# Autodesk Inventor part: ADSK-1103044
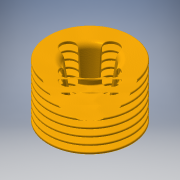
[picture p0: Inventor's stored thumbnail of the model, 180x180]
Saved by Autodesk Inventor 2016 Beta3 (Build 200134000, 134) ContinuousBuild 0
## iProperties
Shininess: 41.0
Length Units: 11272
Angle Units: 11279
Time Units: 11290
Mass Units: 11286
Length Display Precision: 4
Angle Display Precision: 2
Compacted: True
Created: 2000-07
Part Number: ADSK-1103044
Document SubType Name: Modeling
Description: ENGINE HEAD
Mass: 37.1194 g
Surface Area: 215.954 cm^2
Volume: 13.6972 cm^3
Density: 2.71 g/cm^3
Material: Aluminum-6061
Appearance: Yellow
Density: 0.0
Volumn: 0.0
Area: 0.0
PropertySet Name: Model Information
Control State: 0
Master: False
Checked Out: False
Author: Autodesk, Inc.
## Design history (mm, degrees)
node "Revolution1" dims "d6" = 90 deg
  sketch "Sketch2"
    geometry: L1 (17.699, 35.694)-(17.699, 61.094); L2 (17.699, 61.094)-(-5.161, 61.094); L3 (-5.161, 31.884)-(2.459, 31.884); L4 (2.459, 31.884)-(2.459, 35.694); L5 (2.459, 35.694)-(17.699, 35.694); L6 (-5.161, 61.094)-(-5.161, 31.884)
    constraints: 12 end point, 4 perpendicular, 1 parallel, 1 vertical, 1 other
    dimensions: "d0" = 45.72 diameter of L2.end L1; "d1" = 30.48 diameter of L4 L1; "d3" = 29.21 distance between parallel lines of L2 L3; "d5" = 3.81 distance of L3.end L4.end
workaxis "Work Axis1"
workplane "Work Plane1"
workplane "Work Plane3"
node "Revolution2" dims "d12" = 90 deg
  sketch "Sketch3"
    geometry: L1 (0, -20.447)-(0, 20.447) reference; L2 (15.24, -10.795)-(-15.24, -10.795) reference; L3 (-5.999, -10.795)-(-5.999, -8.255); L4 (-5.999, -8.255)-(-7.938, -8.255); L5 (-7.938, -8.255)-(-11.15, 14.605); L6 (22.86, 14.605)-(-22.86, 14.605) reference; L7 (-5.999, -10.795)-(0, -10.795); L8 (-11.15, 14.605)-(0, 14.605); L9 (0, 14.605)-(0, -10.795)
    constraints: 12 end point, 3 perpendicular, 2 midpoint, 2 point on line
    dimensions: "d8" = 11.99896 diameter of L3 L1; "d9" = 2.54 distance between parallel lines of L2 L4; "d10" = 8 deg angle of L1 L5; "d11" = 15.875 diameter of L4.end L1
node "Fillet1" dims "d13" = 3.175
node "Extrusion1" dims "d16" = 25.4, "d17" = 0
  sketch "Sketch4" dims "d14" = 11.5
    geometry: C1 r 22.86 at (0, 0) reference; C2 r 13.91 at (0, 0) reference; C3 r 4.128 at (0, 11.5); 1 further point
    constraints: 2 vertical alignment, 1 centre point, 1 coincident, 2 other
    dimensions: "d15" = 8.255 diameter of C3
node "Circular Pattern1" dims "d18" = 40, "d20" = 90 deg
workplane "Work Plane2"
node "Revolution3" dims "d46" = 90 deg
  sketch "Sketch5"
    geometry: L1 (11.872, 10.766)-(-8.255, 7.938) reference; L2 (14.605, -22.86)-(14.605, 22.86) reference; L3 (-13.272, 25.4)-(-10.605, 25.4); L4 (-10.605, 25.4)-(-10.605, 16.906); L5 (-13.272, 16.906)-(-13.272, 25.4); L6 (-9.335, 25.4)-(-6.668, 25.4); L7 (-6.668, 25.4)-(-6.668, 10.16); L8 (-6.668, 10.16)-(-9.335, 10.16); L9 (-9.335, 10.16)-(-9.335, 25.4); L10 (-5.398, 25.4)-(-2.731, 25.4); L11 (-2.731, 25.4)-(-2.731, 10.477); L12 (-2.731, 10.477)-(-5.398, 10.477); L13 (-5.398, 10.477)-(-5.398, 25.4); L14 (-1.461, 25.4)-(1.206, 25.4); L15 (1.206, 25.4)-(1.206, 10.795); L16 (1.206, 10.795)-(-1.461, 10.795); L17 (-1.461, 10.795)-(-1.461, 25.4); L18 (2.476, 25.4)-(5.143, 25.4); L19 (5.143, 25.4)-(5.143, 11.112); L20 (5.143, 11.112)-(2.476, 11.112); L21 (2.476, 11.112)-(2.476, 25.4); L22 (6.413, 25.4)-(9.08, 25.4); L23 (9.08, 25.4)-(9.08, 11.43); L24 (9.08, 11.43)-(6.413, 11.43); L25 (6.413, 11.43)-(6.413, 25.4); L26 (10.35, 25.4)-(13.017, 25.4); L27 (13.017, 25.4)-(13.017, 11.747); L28 (13.017, 11.747)-(10.35, 11.747); L29 (10.35, 11.747)-(10.35, 25.4); L30 (-20.447, 0)-(20.447, 0) reference; L31 (-10.605, 16.906)-(-13.272, 16.906)
    constraints: 56 end point, 13 parallel, 8 perpendicular, 7 horizontal, 6 collinear, 6 point on line
    dimensions: "d22" = 2.667 distance between parallel lines of L27 L29; "d23" = 1.5875 distance between parallel lines of L2 L27; "d24" = 1.27 distance between parallel lines of L29 L23; "d25" = 1.27 distance between parallel lines of L25 L19 (= d24); "d26" = 1.27 distance between parallel lines of L21 L15 (= d24); "d27" = 1.27 distance between parallel lines of L17 L11 (= d29); "d28" = 1.27 distance between parallel lines of L7 L13; "d29" = 1.27 distance between parallel lines of L9 L4 (= d24); "d33" = 25.4 distance from line of L30 L26.end; "d38" = 0.3175 vertical distance of L7.end L12.end (= d37); "d39" = 0.3175 vertical distance of L11.end L16.end (= d38); "d40" = 0.3175 vertical distance of L15.end L19.end (= d39); "d41" = 0.3175 vertical distance of L19.end L23.end (= d40); "d42" = 0.3175 vertical distance of L23.end L27.end (= d41)
node "Extrusion2" dims "d48" = 1.5875, "d49" = 0
  sketch "Sketch6"
    geometry: A1 r 4.128 centre (0, 11.5) between (-3.609, 9.497) and (-1.721, 7.749) reference; 2 further points
    constraints: 1 coincident, 3 other
node "Circular Pattern3" dims "d61" = 40, "d63" = 360 deg
node "Fillet3" dims "d67" = 0.508
node "Fillet4" dims "d80" = 0.381
node "Fillet5" dims "d81" = 0.381
node "Hole1" dims "d50" = 2.90068, "d51" = 9.525, "d52" = 6.35, "d53" = 60 deg, "d54" = 19.05, "d55" = 118 deg, "d85" = 12.7
  sketch "Sketch7"
    geometry: C1 r 4.128 at (0, 0) reference
node "Circular Pattern4" dims "d64" = 40, "d66" = 360 deg
node "Fillet6" dims "d82" = 0.381
node "Fillet7" dims "d83" = 0.381
node "Fillet8" dims "d84" = 0.381
body "Solid1"
other parameters: "d7" = 0, "d21" = 45 deg, "d35" = 0.3175, "d36" = 0.3175 (= d35), "d37" = 0.3175 (= d36), "d95" = 90 deg
